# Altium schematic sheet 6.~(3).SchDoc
size 609 x 444 mm
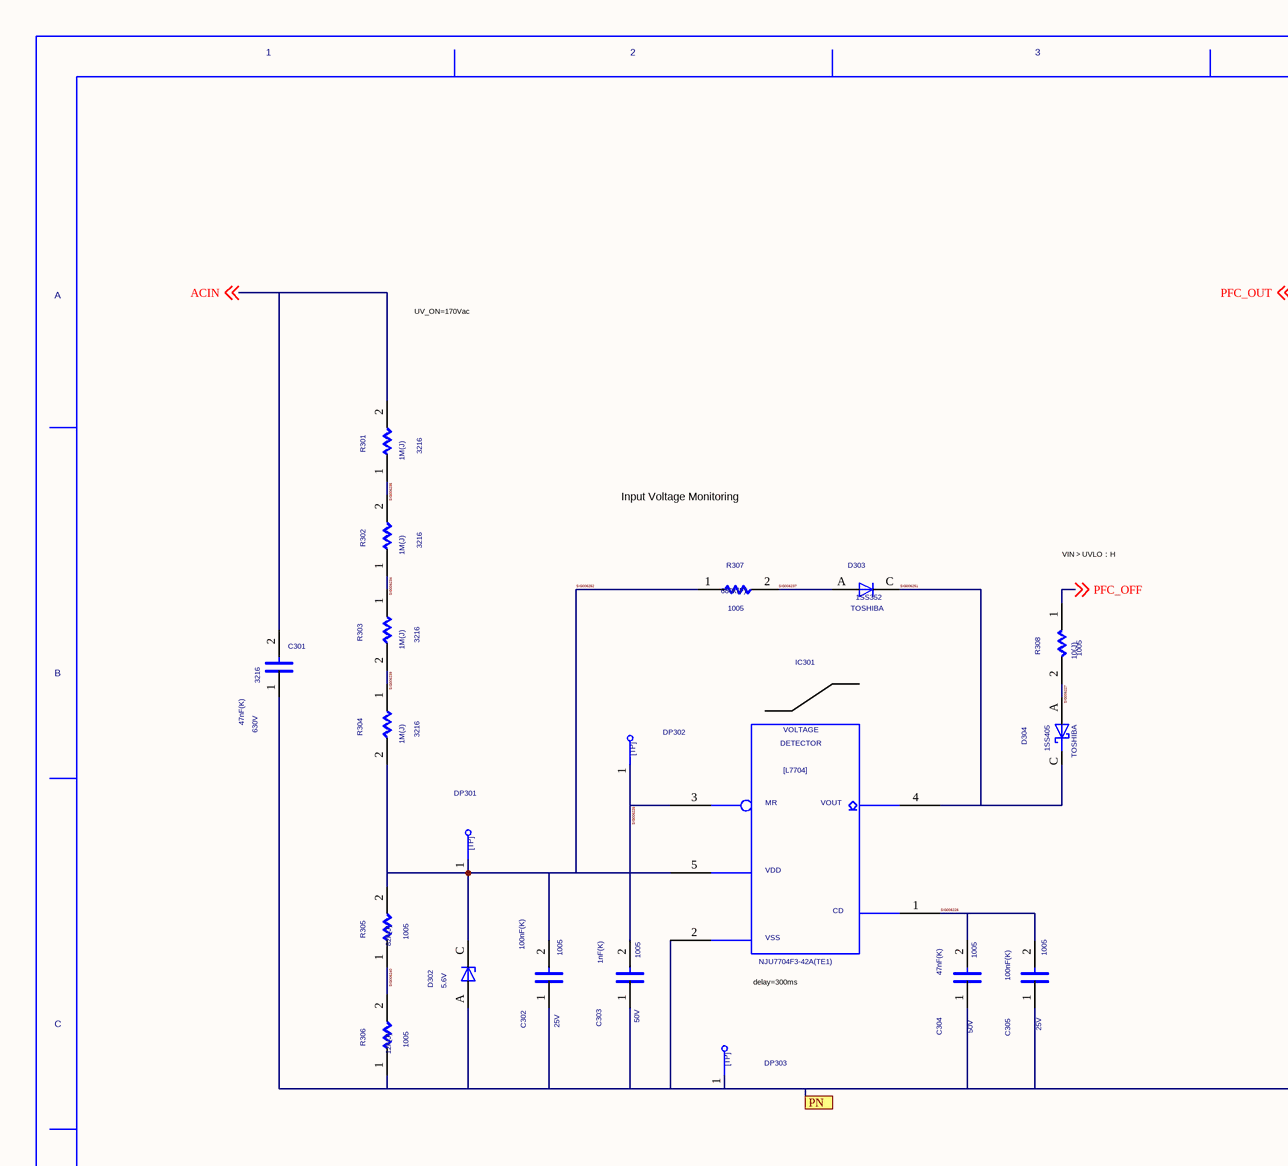
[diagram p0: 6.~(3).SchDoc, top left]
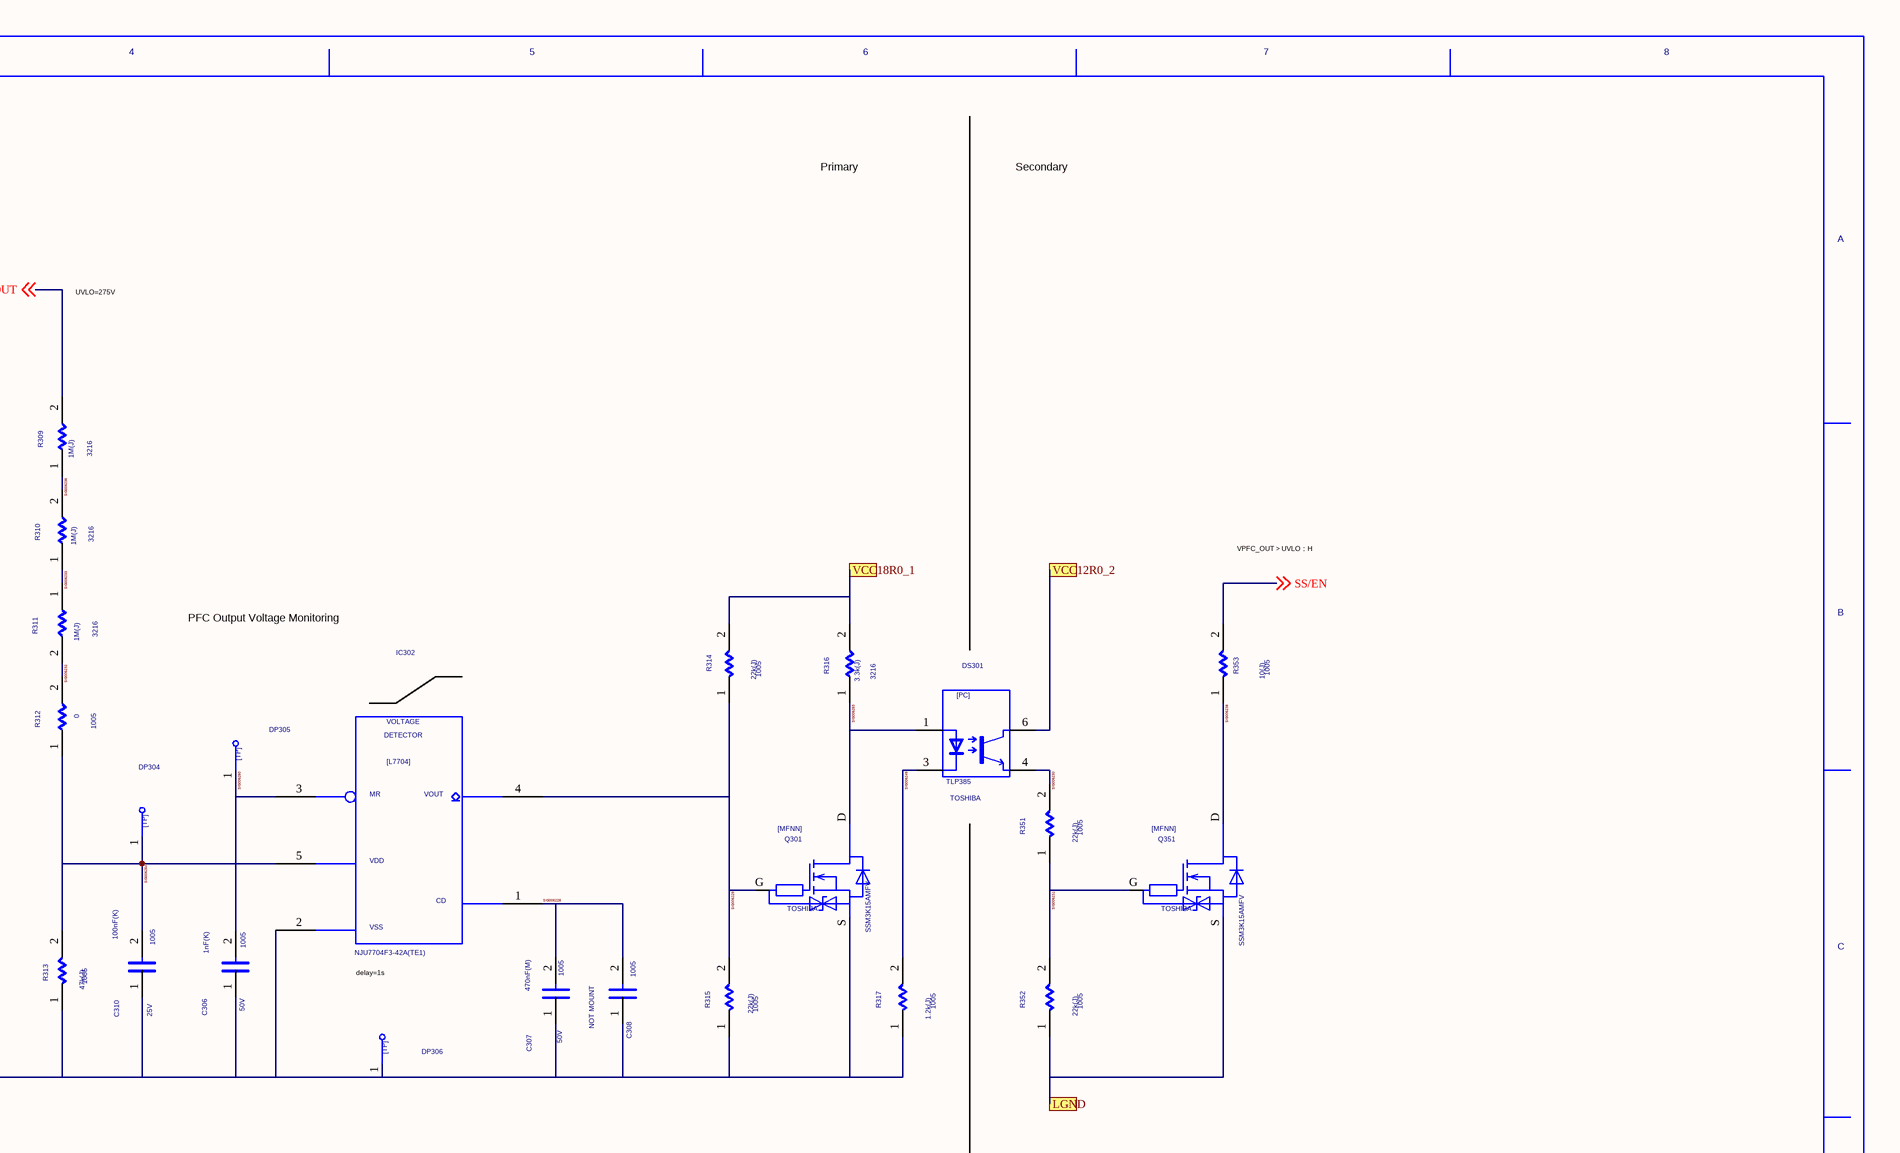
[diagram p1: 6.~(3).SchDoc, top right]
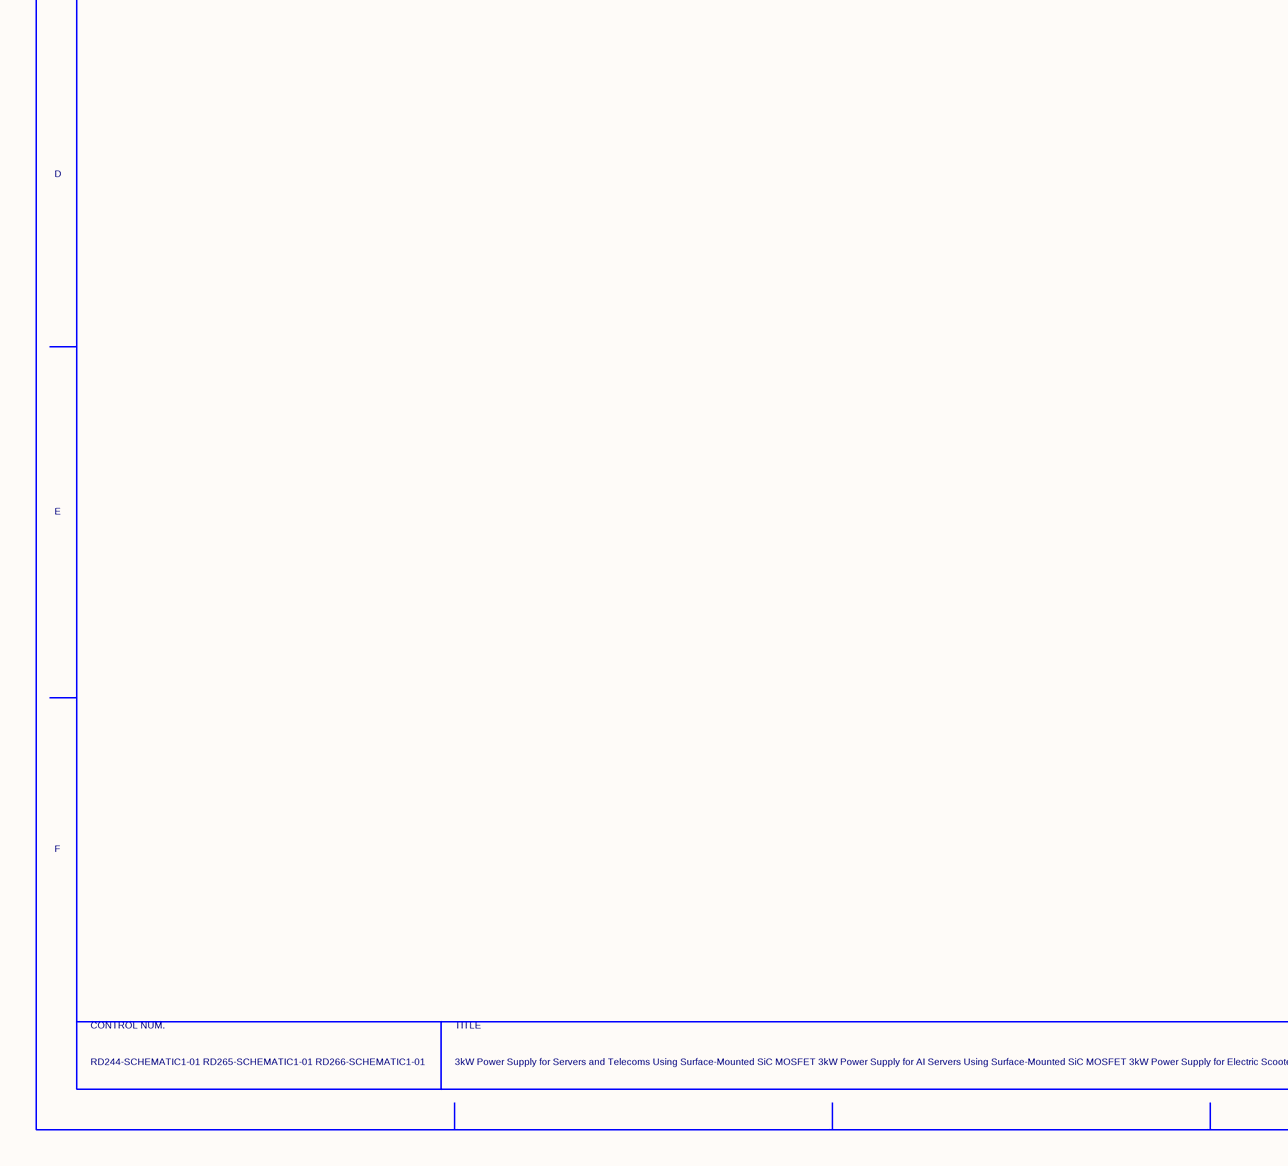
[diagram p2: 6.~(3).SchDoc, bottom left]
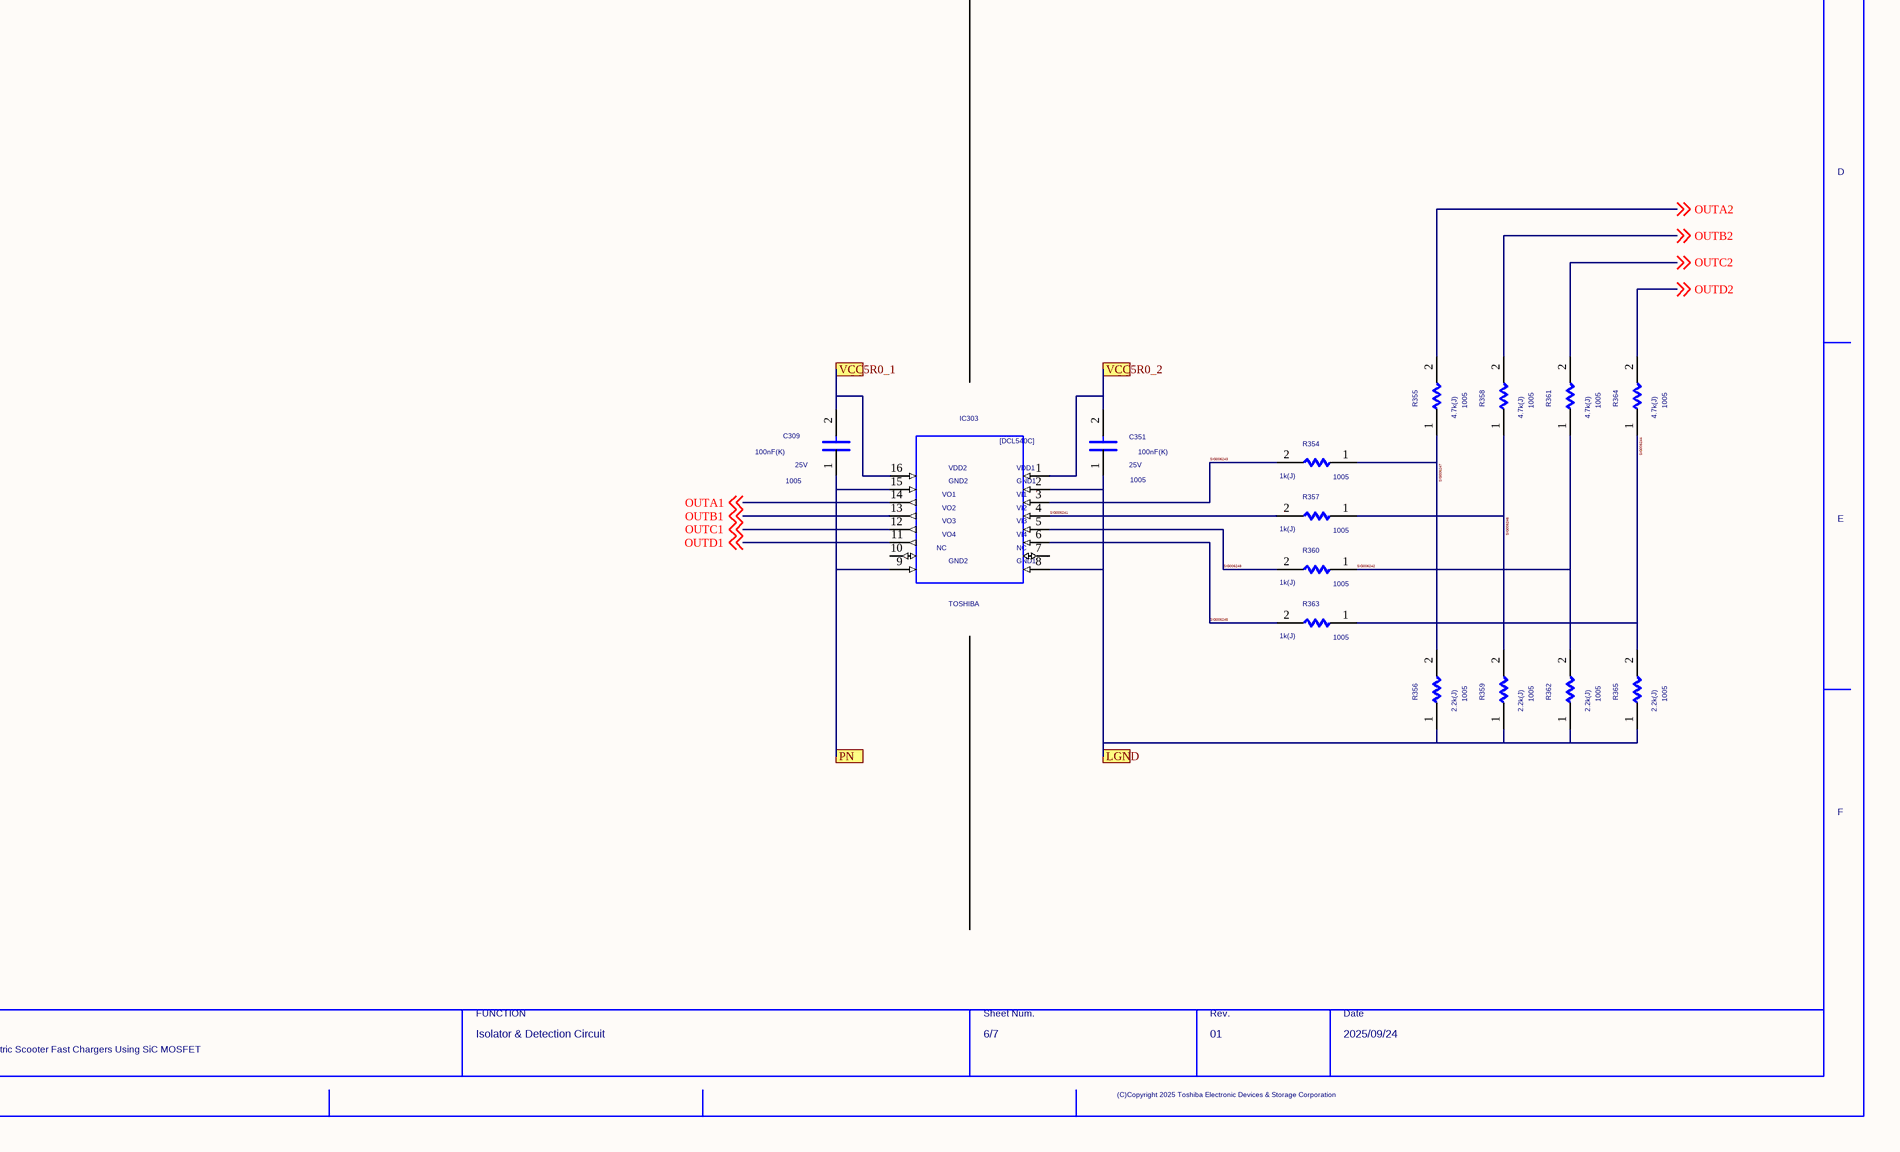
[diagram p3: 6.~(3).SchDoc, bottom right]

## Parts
C301  VAL1: 47nF(K)  VAL2: 630V  SIZECODESMD: 3216  (hidden comment: C)
C302  VAL1: 100nF(K)  VAL2: 25V  SIZECODESMD: 1005  (hidden comment: C)
C303  VAL1: 1nF(K)  VAL2: 50V  SIZECODESMD: 1005  (hidden comment: C)
C304  VAL1: 47nF(K)  VAL2: 50V  SIZECODESMD: 1005  (hidden comment: C)
C305  VAL1: 100nF(K)  VAL2: 25V  SIZECODESMD: 1005  (hidden comment: C)
C306  VAL1: 1nF(K)  VAL2: 50V  SIZECODESMD: 1005  (hidden comment: C)
C307  VAL1: 470nF(M)  VAL2: 50V  SIZECODESMD: 1005  (hidden comment: C)
C308  NOTMOUNT: NOT MOUNT  SIZECODESMD: 1005  (hidden comment: C)
C309  VAL1: 100nF(K)  VAL2: 25V  SIZECODESMD: 1005  (hidden comment: C)
C310  VAL1: 100nF(K)  VAL2: 25V  SIZECODESMD: 1005  (hidden comment: C)
C351  VAL1: 100nF(K)  VAL2: 25V  SIZECODESMD: 1005  (hidden comment: C)
D302  VAL1: 5.6V  (hidden comment: ZenerDiode_USC-01)
D303  USERCOMPTEXT3: TOSHIBA  VAL3: 1SS352  (hidden comment: D)
D304  USERCOMPTEXT3: TOSHIBA  (hidden comment: 1SS405)
DP301  TP  (value not drawn)
DP302  TP  (value not drawn)
DP303  TP  (value not drawn)
DP304  TP  (value not drawn)
DP305  TP  (value not drawn)
DP306  TP  (value not drawn)
DS301  USERCOMPTEXT3: TOSHIBA  (hidden comment: TLP385)
IC301  VAL3: NJU7704F3-42A(TE1)  (hidden comment: L7704)
IC302  VAL3: NJU7704F3-42A(TE1)  (hidden comment: L7704)
IC303  USERCOMPTEXT3: TOSHIBA  (hidden comment: DCL540C01)
Q301  USERCOMPTEXT3: TOSHIBA  VAL3: SSM3K15AMFV  (hidden comment: MFNN)
Q351  USERCOMPTEXT3: TOSHIBA  VAL3: SSM3K15AMFV  (hidden comment: MFNN)
R301  VAL1: 1M(J)  SIZECODESMD: 3216  (hidden comment: R)
R302  VAL1: 1M(J)  SIZECODESMD: 3216  (hidden comment: R)
R303  VAL1: 1M(J)  SIZECODESMD: 3216  (hidden comment: R)
R304  VAL1: 1M(J)  SIZECODESMD: 3216  (hidden comment: R)
R305  VAL1: 82k(J)  SIZECODESMD: 1005  (hidden comment: R)
R306  VAL1: 12k(J)  SIZECODESMD: 1005  (hidden comment: R)
R307  VAL1: 680k(F)  SIZECODESMD: 1005  (hidden comment: R)
R308  VAL1: 10(J)  SIZECODESMD: 1005  (hidden comment: R)
R309  VAL1: 1M(J)  SIZECODESMD: 3216  (hidden comment: R)
R310  VAL1: 1M(J)  SIZECODESMD: 3216  (hidden comment: R)
R311  VAL1: 1M(J)  SIZECODESMD: 3216  (hidden comment: R)
R312  VAL1: 0  SIZECODESMD: 1005  (hidden comment: R)
R313  VAL1: 47k(J)  SIZECODESMD: 1005  (hidden comment: R)
R314  VAL1: 22k(J)  SIZECODESMD: 1005  (hidden comment: R)
R315  VAL1: 22k(J)  SIZECODESMD: 1005  (hidden comment: R)
R316  VAL1: 3.3k(J)  SIZECODESMD: 3216  (hidden comment: R)
R317  VAL1: 1.2k(J)  SIZECODESMD: 1005  (hidden comment: R)
R351  VAL1: 22k(J)  SIZECODESMD: 1005  (hidden comment: R)
R352  VAL1: 22k(J)  SIZECODESMD: 1005  (hidden comment: R)
R353  VAL1: 10(J)  SIZECODESMD: 1005  (hidden comment: R)
R354  VAL1: 1k(J)  SIZECODESMD: 1005  (hidden comment: R)
R355  VAL1: 4.7k(J)  SIZECODESMD: 1005  (hidden comment: R)
R356  VAL1: 2.2k(J)  SIZECODESMD: 1005  (hidden comment: R)
R357  VAL1: 1k(J)  SIZECODESMD: 1005  (hidden comment: R)
R358  VAL1: 4.7k(J)  SIZECODESMD: 1005  (hidden comment: R)
R359  VAL1: 2.2k(J)  SIZECODESMD: 1005  (hidden comment: R)
R360  VAL1: 1k(J)  SIZECODESMD: 1005  (hidden comment: R)
R361  VAL1: 4.7k(J)  SIZECODESMD: 1005  (hidden comment: R)
R362  VAL1: 2.2k(J)  SIZECODESMD: 1005  (hidden comment: R)
R363  VAL1: 1k(J)  SIZECODESMD: 1005  (hidden comment: R)
R364  VAL1: 4.7k(J)  SIZECODESMD: 1005  (hidden comment: R)
R365  VAL1: 2.2k(J)  SIZECODESMD: 1005  (hidden comment: R)
U?  DATE: 2025/09/24  DRAWINGNUMBER: RD244-SCHEMATIC1-01 / RD265-SCHEMATIC1-01 / RD266-SCHEMATIC1-01  TITLE: 3kW Power Supply for Servers and Telecoms Using Surface-Mounted SiC MOSFET / 3kW Power Supply for AI Servers Using Surface-Mounted SiC MOSFET / 3kW Power Supply for Electric Scooter Fast Chargers Using SiC MOSFET  FUNCTION: Isolator & Detection Circuit  SHEETNUMBER: 6/7  REVISION: 01  (hidden comment: WAKU_DEF_A3_1)

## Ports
LGND, PN, VCC5R0_1, VCC5R0_2, VCC12R0_2, VCC18R0_1

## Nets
ACIN: C301.2 R301.2 ; off-sheet ACIN
LGND: C351.1 IC303.2 IC303.8 Q351.S R352.1 R356.1 R359.1 R362.1 R365.1 ; port LGND
OUTA1: IC303.14 ; off-sheet OUTA1
OUTA2: R355.2 ; off-sheet OUTA2
OUTB1: IC303.13 ; off-sheet OUTB1
OUTB2: R358.2 ; off-sheet OUTB2
OUTC1: IC303.12 ; off-sheet OUTC1
OUTC2: R361.2 ; off-sheet OUTC2
OUTD1: IC303.11 ; off-sheet OUTD1
OUTD2: R364.2 ; off-sheet OUTD2
PFC_OFF: R308.1 ; off-sheet PFC_OFF
PFC_OUT: R309.2 ; off-sheet PFC_OUT
PN: C301.1 C302.1 C303.1 C304.1 C305.1 C306.1 C307.1 C308.1 C309.1 C310.1 D302.A DP303.1 DP306.1 IC301.2 IC302.2 IC303.9 IC303.15 Q301.S R306.1 R313.1 R315.1 R317.1 ; port PN
SIG006225: C303.2 DP302.1 IC301.3
SIG006226: C304.2 C305.2 IC301.1
SIG006227: D304.A R308.2
SIG006228: C307.2 C308.2 IC302.1
SIG006229: IC302.4 Q301.G R314.1 R315.2
SIG006230: DS301.4 R351.2
SIG006231: Q351.G R351.1 R352.2
SIG006232: R311.2 R312.2
SIG006233: R310.1 R311.1
SIG006234: R302.1 R303.1
SIG006235: R301.1 R302.2
SIG006236: R309.1 R310.2
SIG006237: D303.A R307.2
SIG006238: Q351.D R353.1
SIG006239: R303.2 R304.1
SIG006240: R305.1 R306.2
SIG006241: IC303.4 R357.2
SIG006242: R360.1 R361.1 R362.2
SIG006243: IC303.3 R354.2
SIG006244: R363.1 R364.1 R365.2
SIG006245: IC303.6 R363.2
SIG006246: R357.1 R358.1 R359.2
SIG006247: R354.1 R355.1 R356.2
SIG006248: IC303.5 R360.2
SIG006249: DS301.3 R317.2
SIG006250: C306.2 DP305.1 IC302.3
SIG006251: D303.C D304.C IC301.4
SIG006252: C302.2 D302.C DP301.1 IC301.5 R304.2 R305.2 R307.1
SIG006253: DS301.1 Q301.D R316.1
SIG006254: C310.2 DP304.1 IC302.5 R312.1 R313.2
SS/EN: R353.2 ; off-sheet SS/EN
VCC5R0_1: C309.2 IC303.16 ; port VCC5R0_1
VCC5R0_2: C351.2 IC303.1 ; port VCC5R0_2
VCC12R0_2: DS301.6 ; port VCC12R0_2
VCC18R0_1: R314.2 R316.2 ; port VCC18R0_1

Not connected (* = marked no-connect by the designer): IC303 7 10

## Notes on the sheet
- Primary
- Secondary
- UV_ON=170Vac
  UV_OFF=158Vac
- UVLO=275V
- Input Voltage Monitoring
- VIN＞UVLO：H
  VIN＜UVLO：L
- VPFC_OUT＞UVLO：H
  VPFC_OUT＜UVLO：L
- PFC Output Voltage Monitoring
- (near IC301) delay=300ms
- (near IC302) delay=1s

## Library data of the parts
C301 = C_Dup2: OriginalSymbolOrigin: (2540,7620); COMP: PRT_46; MAXGCOUNT: 1; SAVECOUNT: 0
C302 C305 C309 C310 C351 = C_Dup2: SQ_PART_MODEL: CON_100N; OriginalSymbolOrigin: (2540,7620); COMP: PRT_52; MAXGCOUNT: 1; ADSCNVFLAG: ON; ADSCOMPONENTNAME: C_1005; SAVECOUNT: 0
C303 C304 C306 C307 = C_Dup2: OriginalSymbolOrigin: (2540,7620); COMP: PRT_52; MAXGCOUNT: 1; SAVECOUNT: 0
C308 = C_Dup2: VAL1: 10nF(K); VAL2: 50V; OriginalSymbolOrigin: (2540,7620); COMP: PRT_52; MAXGCOUNT: 1; SAVECOUNT: 0
D302 = ZENERDIODE_USC-01: SAVEAREA0: -4630,-153,17114,13055; TIME: 14:49:55; UPDATEUSER: t4887876; UPDATETIME: 08:23:49; SAVECOUNT: 9; OriginalSymbolOrigin: (5080,5080); MAXGCOUNT: 1; ADSCNVFLAG: ON; ADSCOMPONENTNAME: D_ZD; VAL3: XCUZ5V6
D303 = D_Dup1: SAVEAREA0: -225,-91,12804,7836; SAVECOUNT: 3; TIME: 14:49:55; UPDATEUSER: 19870035; UPDATETIME: 14:20:16; VAL1: 1SS352(TPH3,F); OriginalSymbolOrigin: (5080,5080); USERCOMPTEXT2: 80V,0.1A; COMP: PRT_27
D304 = 1SS405: SAVEAREA0: -4630,-153,17114,13055; TIME: 14:49:55; UPDATEUSER: t4887876; UPDATETIME: 11:25:22; SAVECOUNT: 16; CHIPSET: SOD-523; VAL1: 20V; VAL2: 0.05A; OriginalSymbolOrigin: (5080,5080); MAXGCOUNT: 1; ADSCNVFLAG: ON; ADSCOMPONENTNAME: D_SBD
DP301-DP306 = TP: TIME: 16:12:21; UPDATEUSER: fukuda-y; UPDATETIME: 16:18:11; SAVECOUNT: 2; SAVEAREA0: -242,-92,12810,7836; OriginalSymbolOrigin: (0,7620); USERCOMPTEXT1: Φ1.5mm; COMP: DTP815
DS301 = TLP385: TIME: 18:37:26; UPDATEUSER: t4887876; UPDATETIME: 18:41:04; SAVECOUNT: 3; OriginalSymbolOrigin: (5080,17780); GATENO: 1; ADSCNVFLAG: ON
IC301 IC302 = L7704: SAVECOUNT: 23; SAVEAREA0: -14253,-557,65080,48696; TIME: 18:10:57; UPDATEUSER: 19990028; UPDATETIME: 10:41:32; OriginalSymbolOrigin: (7620,45720); MAXGCOUNT: 1; COMP: GDM470001845; ADSCNVFLAG: ON; VAL1: NJU7704F3-25A(TE1); FUNCTION: OTHER
IC303 = DCL540C01: TIME: 11:12:35; UPDATEUSER: t6860224; UPDATETIME: 18:45:42; SAVECOUNT: 6; SAVEAREA0: -81052,-32740,106905,52903; OriginalSymbolOrigin: (5080,27940); MAXGCOUNT: 1; FUNCTION: FXD
Q301 Q351 = MFNN: SAVECOUNT: 25; SAVEAREA0: -2884,-274,25430,18334; TIME: 08:01:03; UPDATEUSER: sato-yr; UPDATETIME: 13:42:20; VAL1: SSM3K15AMFV,L3F(T; OriginalSymbolOrigin: (2540,17780); MAXGCOUNT: 1; COMP: GDM410000663; ADSCNVFLAG: ON; ADSCOMPONENTNAME: Q_MFNN
R301-R304 R309-R311 = R_Dup2: VAL2: 250mW; OriginalSymbolOrigin: (5080,5080); COMP: PRT_5; CHIPSIZE: 1608; MAXGCOUNT: 1; SAVECOUNT: 0
R305-R308 R313-R315 R317 R351-R365 = R_Dup2: VAL2: 63mW; OriginalSymbolOrigin: (5080,5080); COMP: GDM010004481; CHIPSIZE: 1608; MAXGCOUNT: 1; SAVECOUNT: 0
R312 = R_Dup2: VAL2: 63mW; OriginalSymbolOrigin: (5080,5080); MAXGCOUNT: 1; COMP: GDM010004481; CHIPSIZE: 1608
R316 = R_Dup2: SQ_PART_MODEL: RES_4.87K; VAL2: 250mW; OriginalSymbolOrigin: (5080,5080); COMP: PRT_5; CHIPSIZE: 1608; MAXGCOUNT: 1; ADSCNVFLAG: ON; ADSCOMPONENTNAME: R_3216; SAVECOUNT: 0
U? = WAKU_DEF_A3_1: PLOTTIME: HH:MM; SAVEAREA0: 96913,-567914,509243,-368858; TIME: 16:14:05; UPDATEUSER: t5459927; UPDATETIME: 13:12:48; SAVECOUNT: 3; ZONEOFFSETX: 36; ZONEOFFSETY: -24; OriginalSymbolOrigin: (12700,-12700); SHTSAVECOUNT: 262; PAGENUMBER: 6; DESIGNED: TOSHIBA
